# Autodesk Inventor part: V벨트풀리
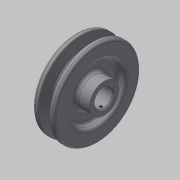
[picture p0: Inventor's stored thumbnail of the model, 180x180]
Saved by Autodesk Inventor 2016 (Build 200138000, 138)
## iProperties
Created: 2015-11
Part Number: V벨트풀리
Material: 강철, 탄소
Document SubType Name: Modeling
Designer: mduedu
Density: 1 g/cm^3
Appearance: 기본값
Author: mduedu
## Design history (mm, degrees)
sketch "스케치1"
  geometry: L1 (-9.5, 0)-(9.5, 0); L2 (0, 0)-(0, 37.7); L3 (-4.825, 37.7)-(-9.5, 37.7); L4 (-9.5, 37.7)-(-9.5, 0); L5 (0, 28.7)-(-2.074, 28.7); L6 (-2.074, 28.7)-(-4.825, 37.7); L7 (4.825, 37.7)-(9.5, 37.7); L8 (9.5, 37.7)-(9.5, 0); L9 (0, 28.7)-(2.074, 28.7); L10 (2.074, 28.7)-(4.825, 37.7); L11 (-9.5, 35)-(9.5, 35); 3 further points
  constraints: 22 end point, 7 point on line, 4 perpendicular, 3 symmetric about line, 1 coincident, 1 horizontal, 1 horizontal alignment, 1 midpoint, 1 vertical
  dimensions: "d0" = 19 distance of L1.start L1.end; "d2" = 75.4 diameter of L2.end L1 (derived); "d3" = 34 deg angle of L10 L6; "d4" = 6.3 distance between parallel lines of L11 L9; "d5" = 2.7 distance between parallel lines of L7 L11; "d6" = 8 distance of point (4, 35) point (-4, 35); "d7" = 70 diameter of L11 L1
revolve "회전1" sketch "스케치1" stored, may be unused: angle "d8" = 90 deg
sketch "스케치2"
  geometry: C1 r 24 at (0, 0); C2 r 13 at (0, 0); 1 further point
  constraints: 2 centre point, 2 coincident
  dimensions: "d9" = 48 diameter of C1; "d10" = 26 diameter of C2
extrude "돌출1" cut sketch "스케치2" distance "d11" = 6; taper "d12" = 0 deg
extrude "돌출3" join sketch "스케치2" distance "d37" = 6; taper "d38" = 0 deg
fillet "모깎기1" dims "d13" = 3
fillet "모깎기2" dims "d14" = 3
fillet "모깎기3" dims "d15" = 1, "d16" = 0.5, "d17" = 2
hole "구멍1" diameter "d20" = 16; stored, may be unused: countersink angle "d24" = 90 deg, drill point angle "d26" = 118 deg; dims "d21" = 6, "d22" = 4, "d23" = 2, "d25" = 8, "d53" = 10, "d54" = 10
sketch "스케치3"
  geometry: L1 (-2.5, 0)-(2.5, 0); L2 (2.5, 0)-(2.5, 10.3); L3 (2.5, 10.3)-(-2.5, 10.3); L4 (-2.5, 10.3)-(-2.5, 0); 2 further points
  constraints: 8 end point, 2 parallel, 1 coincident, 1 horizontal, 1 midpoint, 1 perpendicular
  dimensions: "d27" = 5 distance of L2.end L3.end; "d29" = 10.3 distance of L3.end L1.start
extrude "돌출2" cut sketch "스케치3" stored distance "d30" = 6; taper "d31" = 0 deg
chamfer "모따기1" distance "d32" = 1; stored, may be unused: second distance "d33" = 2, angle "d34" = 45 deg
node "작업 평면1"
sketch "스케치4"
  geometry: L1 (19, -27)-(19, 27) reference; 2 further points
  constraints: 1 horizontal alignment
  dimensions: "d52" = 22 distance from line of L1 point (-3, 0)
hole "구멍2" sketch "스케치4" at (-3, 0) diameter "d42" = 2.459; stored, may be unused: countersink angle "d46" = 90 deg, drill point angle "d48" = 118 deg; dims "d43" = 6, "d44" = 4, "d45" = 2, "d47" = 8
chamfer "모따기3" distance "d58" = 1; stored, may be unused: second distance "d59" = 2, angle "d60" = 45 deg
node "솔리드1"
mirror "대칭1"
